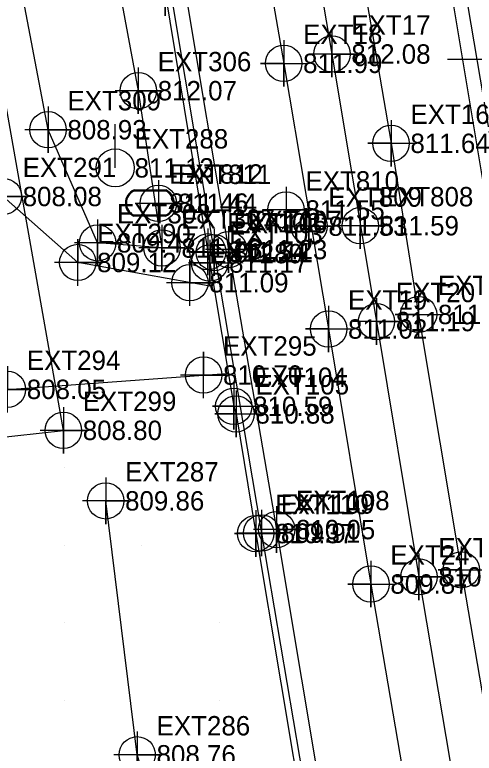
# Model space of a CAD drawing. Extents: x 1762120 to 1766775, y 709485 to 712965.
# Drawn here: x 1763773.6 to 1763832.9, y 712653.2 to 712748.4 of the extents above; entities that cross this region are included whole.
import ezdxf

# ---------------------------------------------------------------- set-up
doc = ezdxf.new("R2010")
doc.units = 0
for name, color, linetype in [('Exist DTM Breakline', 7, 'Continuous'), ('Exist DTM Breakline Cogo Elevation', 7, 'Continuous'), ('Exist DTM Breakline Cogo Number', 7, 'Continuous'), ('Exist DTM Breakline Cogo Point CELL', 7, 'Continuous'), ('Exist DTM Crownline', 7, 'Continuous'), ('Exist DTM Crownline Cogo Elevation', 7, 'Continuous'), ('Exist DTM Crownline Cogo Number', 7, 'Continuous'), ('Exist DTM Crownline Cogo Point CELL', 7, 'Continuous'), ('Exist DTM Drainline', 7, 'Continuous'), ('Exist DTM Drainline Cogo Elevation', 7, 'Continuous'), ('Exist DTM Drainline Cogo Number', 7, 'Continuous'), ('Exist DTM Drainline Cogo Point CELL', 7, 'Continuous'), ('Exist DTM QL2 LIDAR Elevation Point', 7, 'Continuous'), ('Exist Other Culture Fence Line', 7, 'Continuous'), ('Exist Other Culture Fence Line Cogo Elevation', 7, 'Continuous'), ('Exist Other Culture Fence Line Cogo Number', 7, 'Continuous'), ('Exist Other Culture Fence Line Cogo Point CELL', 7, 'Continuous'), ('Exist Roads Curbs', 7, 'Continuous'), ('Exist Roads Curbs Cogo Elevation', 7, 'Continuous'), ('Exist Roads Curbs Cogo Number', 7, 'Continuous'), ('Exist Roads Curbs Cogo Point CELL', 7, 'Continuous'), ('Exist Roads EOP', 7, 'Continuous'), ('Exist Roads EOP Cogo Elevation', 7, 'Continuous'), ('Exist Roads EOP Cogo Number', 7, 'Continuous'), ('Exist Roads EOP Cogo Point CELL', 7, 'Continuous'), ('Exist Roads EOT', 7, 'Continuous'), ('Exist Roads EOT Cogo Elevation', 7, 'Continuous'), ('Exist Roads EOT Cogo Number', 7, 'Continuous'), ('Exist Roads EOT Cogo Point CELL', 7, 'Continuous'), ('Exist Roads Soil', 7, 'Continuous'), ('Exist Roads Soil Cogo Elevation', 7, 'Continuous'), ('Exist Roads Soil Cogo Number', 7, 'Continuous'), ('Exist Roads Soil Cogo Point CELL', 7, 'Continuous'), ('Exist Utilities Power Joint Use Telephone CELL', 7, 'Continuous'), ('Exist Utilities Power Pole CELL', 7, 'Continuous'), ('Exist Utilities Power Pole Cogo Elevation', 7, 'Continuous'), ('Exist Utilities Power Pole Cogo Number', 7, 'Continuous'), ('Exist Utilities Water Meter CELL', 7, 'Continuous'), ('Exist Utilities Water Meter Cogo Elevation', 7, 'Continuous'), ('Exist Utilities Water Meter Cogo Number', 7, 'Continuous'), ('Exist Utilities Water UG Line SUE LOS C Cogo Elevation', 7, 'Continuous'), ('Exist Utilities Water UG Line SUE LOS C Cogo Number', 7, 'Continuous'), ('Exist Utilities Water UG Line SUE LOS C Cogo Point CELL', 7, 'Continuous')]:
    doc.layers.add(name, color=color, linetype=linetype)

msp = doc.modelspace()

# ---------------------------------------------------------------- linework, layer by layer
at = {"layer": 'Exist DTM Breakline'}
for points in [[(1763768.874, 712844.443), (1763776.006, 712808.452), (1763782.443, 712776.817), (1763789.545, 712738.641), (1763792.599, 712718.345), (1763784.294, 712719.006), (1763777.898, 712733.601), (1763771.211, 712768.686), (1763764.647, 712800.553), (1763763.195, 712827.976)], [(1763816.336, 712568.975), (1763813.77, 712594.344), (1763809.401, 712612.263), (1763805.117, 712594.603), (1763799.817, 712620.266), (1763789.401, 712652.954), (1763785.334, 712685.719)]]:
    msp.add_lwpolyline(points, dxfattribs=at)
at = {"layer": 'Exist DTM Breakline Cogo Point CELL'}
for points in [[(1763789.545, 712741.641), (1763789.545, 712735.641), (1763789.545, 712738.641), (1763792.545, 712738.641), (1763786.545, 712738.641)], [(1763777.898, 712736.601), (1763777.898, 712730.601), (1763777.898, 712733.601), (1763780.898, 712733.601), (1763774.898, 712733.601)], [(1763784.294, 712722.006), (1763784.294, 712716.006), (1763784.294, 712719.006), (1763787.294, 712719.006), (1763781.294, 712719.006)], [(1763792.599, 712721.345), (1763792.599, 712715.345), (1763792.599, 712718.345), (1763795.599, 712718.345), (1763789.599, 712718.345)], [(1763785.334, 712688.719), (1763785.334, 712682.719), (1763785.334, 712685.719), (1763788.334, 712685.719), (1763782.334, 712685.719)], [(1763789.401, 712655.954), (1763789.401, 712649.954), (1763789.401, 712652.954), (1763792.401, 712652.954), (1763786.401, 712652.954)]]:
    msp.add_lwpolyline(points, dxfattribs=at)
for centre in [(1763789.545, 712738.641), (1763777.898, 712733.601), (1763784.294, 712719.006), (1763792.599, 712718.345), (1763785.334, 712685.719), (1763789.401, 712652.954)]:
    msp.add_circle(centre, 2.344, dxfattribs=at)
at = {"layer": 'Exist DTM Crownline'}
msp.add_lwpolyline([(1763783.92, 712926.058), (1763790.262, 712887.319), (1763795.183, 712859.532), (1763803.032, 712808.629), (1763808.926, 712776.275), (1763814.523, 712743.371), (1763820.27, 712708.85), (1763825.749, 712675.916), (1763832.222, 712637.522), (1763836.733, 712610.54), (1763843.626, 712568.925)], dxfattribs=at)
at = {"layer": 'Exist DTM Crownline Cogo Point CELL'}
for points in [[(1763814.523, 712746.371), (1763814.523, 712740.371), (1763814.523, 712743.371), (1763817.523, 712743.371), (1763811.523, 712743.371)], [(1763820.27, 712711.85), (1763820.27, 712705.85), (1763820.27, 712708.85), (1763823.27, 712708.85), (1763817.27, 712708.85)], [(1763825.749, 712678.916), (1763825.749, 712672.916), (1763825.749, 712675.916), (1763828.749, 712675.916), (1763822.749, 712675.916)]]:
    msp.add_lwpolyline(points, dxfattribs=at)
for centre in [(1763814.523, 712743.371), (1763820.27, 712708.85), (1763825.749, 712675.916)]:
    msp.add_circle(centre, 2.344, dxfattribs=at)
at = {"layer": 'Exist DTM Drainline'}
for points in [[(1763888.176, 712675.965), (1763883.465, 712673.426), (1763879.421, 712672.239), (1763861.295, 712669.219), (1763855.834, 712669.139), (1763849.992, 712671.404), (1763845.815, 712675.27), (1763843.641, 712680.197), (1763837.254, 712719.085), (1763830.877, 712756.626), (1763824.422, 712795.511), (1763818.53, 712833.611)], [(1763781.288, 712825.282), (1763786.304, 712795.661), (1763793.687, 712751.498), (1763799.331, 712717.754), (1763805.438, 712681.563), (1763811.952, 712643.035), (1763816.532, 712615.56)]]:
    msp.add_lwpolyline(points, dxfattribs=at)
at = {"layer": 'Exist DTM Drainline Cogo Point CELL'}
for points in [[(1763799.331, 712720.754), (1763799.331, 712714.754), (1763799.331, 712717.754), (1763802.331, 712717.754), (1763796.331, 712717.754)], [(1763805.438, 712684.563), (1763805.438, 712678.563), (1763805.438, 712681.563), (1763808.438, 712681.563), (1763802.438, 712681.563)]]:
    msp.add_lwpolyline(points, dxfattribs=at)
for centre in [(1763799.331, 712717.754), (1763805.438, 712681.563)]:
    msp.add_circle(centre, 2.344, dxfattribs=at)
at = {"layer": 'Exist DTM QL2 LIDAR Elevation Point'}
for p, q in [((1763780, 712690), (1763780, 712690)), ((1763790, 712690), (1763790, 712690)), ((1763780, 712680), (1763780, 712680)), ((1763790, 712680), (1763790, 712680)), ((1763780, 712670), (1763780, 712670)), ((1763800, 712670), (1763800, 712670)), ((1763780, 712660), (1763780, 712660)), ((1763800, 712660), (1763800, 712660))]:
    msp.add_line(p, q, dxfattribs=at)
at = {"layer": 'Exist Other Culture Fence Line'}
msp.add_lwpolyline([(1763735.91, 712689.964), (1763779.878, 712694.817), (1763760.773, 712802.969), (1763712.076, 712799.335)], dxfattribs=at)
at = {"layer": 'Exist Other Culture Fence Line Cogo Point CELL'}
msp.add_lwpolyline([(1763779.878, 712697.817), (1763779.878, 712691.817), (1763779.878, 712694.817), (1763782.878, 712694.817), (1763776.878, 712694.817)], dxfattribs=at)
msp.add_circle((1763779.878, 712694.817), 2.344, dxfattribs=at)
at = {"layer": 'Exist Roads Curbs'}
msp.add_lwpolyline([(1763764.468, 712921.993), (1763771.224, 712881.371), (1763777.799, 712842.52), (1763785.017, 712799.156), (1763793.002, 712751.297), (1763798.517, 712717.85), (1763798.751, 712716.41), (1763801.856, 712697.916), (1763802.154, 712696.936), (1763804.688, 712681.498), (1763811.149, 712642.967), (1763816.501, 712611.824), (1763823.372, 712570.121)], dxfattribs=at)
at = {"layer": 'Exist Roads Curbs Cogo Point CELL'}
for points in [[(1763793.002, 712754.297), (1763793.002, 712748.297), (1763793.002, 712751.297), (1763790.272, 712751.297), (1763796.002, 712751.297)], [(1763798.517, 712720.85), (1763798.517, 712714.85), (1763798.517, 712717.85), (1763795.787, 712717.85), (1763801.517, 712717.85)], [(1763798.751, 712719.41), (1763798.751, 712713.41), (1763798.751, 712716.41), (1763796.021, 712716.41), (1763801.751, 712716.41)], [(1763801.856, 712700.916), (1763801.856, 712694.916), (1763801.856, 712697.916), (1763799.126, 712697.916), (1763804.856, 712697.916)], [(1763802.154, 712699.936), (1763802.154, 712693.936), (1763802.154, 712696.936), (1763799.424, 712696.936), (1763805.154, 712696.936)], [(1763804.688, 712684.498), (1763804.688, 712678.498), (1763804.688, 712681.498), (1763801.958, 712681.498), (1763807.688, 712681.498)]]:
    msp.add_lwpolyline(points, dxfattribs=at)
for centre in [(1763798.517, 712717.85), (1763798.751, 712716.41), (1763801.856, 712697.916), (1763802.154, 712696.936), (1763804.688, 712681.498)]:
    msp.add_circle(centre, 2.344, dxfattribs=at)
at = {"layer": 'Exist Roads EOP'}
for points in [[(1763767.083, 712922.223), (1763773.823, 712881.974), (1763780.335, 712842.895), (1763788.848, 712791.154), (1763795.539, 712751.806), (1763801.2, 712718.139), (1763807.385, 712682.013), (1763813.812, 712643.387), (1763818.936, 712612.35), (1763825.965, 712570.729)], [(1763872.939, 712669.264), (1763861.771, 712667.397), (1763856.129, 712667.205), (1763850.394, 712669.068), (1763848.283, 712670.385), (1763843.436, 712675.406), (1763841.767, 712679.86), (1763835.931, 712715.544), (1763829.184, 712756.072), (1763822.427, 712796.443), (1763817.324, 712826.974), (1763816.07, 712838.811), (1763818.954, 712848.93), (1763823.982, 712854.424), (1763830.822, 712857.794), (1763839.256, 712859.239)]]:
    msp.add_lwpolyline(points, dxfattribs=at)
at = {"layer": 'Exist Roads EOP Cogo Point CELL'}
for points in [[(1763801.2, 712721.139), (1763801.2, 712715.139), (1763801.2, 712718.139), (1763804.2, 712718.139), (1763798.2, 712718.139)], [(1763807.385, 712685.013), (1763807.385, 712679.013), (1763807.385, 712682.013), (1763810.385, 712682.013), (1763804.385, 712682.013)]]:
    msp.add_lwpolyline(points, dxfattribs=at)
for centre in [(1763801.2, 712718.139), (1763807.385, 712682.013)]:
    msp.add_circle(centre, 2.344, dxfattribs=at)
at = {"layer": 'Exist Roads EOT'}
for points in [[(1763789.832, 712926.884), (1763795.992, 712888.052), (1763800.75, 712859.942), (1763807.254, 712820.955), (1763816.86, 712762.721), (1763822.148, 712731.849), (1763825.695, 712709.767), (1763831.213, 712676.817), (1763837.744, 712638.56), (1763842.2, 712611.183), (1763849.139, 712569.759)], [(1763777.488, 712924.55), (1763781.487, 712903.204), (1763789.164, 712854.697), (1763797.205, 712808.308), (1763802.541, 712775.258), (1763808.303, 712742.168), (1763814.095, 712707.894), (1763819.559, 712674.99), (1763826.1, 712636.377), (1763830.485, 712609.669), (1763837.441, 712567.81)]]:
    msp.add_lwpolyline(points, dxfattribs=at)
at = {"layer": 'Exist Roads EOT Cogo Point CELL'}
for points in [[(1763808.303, 712745.168), (1763808.303, 712739.168), (1763808.303, 712742.168), (1763805.303, 712742.168), (1763811.303, 712742.168)], [(1763822.148, 712734.849), (1763822.148, 712728.849), (1763822.148, 712731.849), (1763819.148, 712731.849), (1763825.148, 712731.849)], [(1763825.695, 712712.767), (1763825.695, 712706.767), (1763825.695, 712709.767), (1763822.695, 712709.767), (1763828.695, 712709.767)], [(1763814.095, 712710.894), (1763814.095, 712704.894), (1763814.095, 712707.894), (1763811.095, 712707.894), (1763817.095, 712707.894)], [(1763831.213, 712679.817), (1763831.213, 712673.817), (1763831.213, 712676.817), (1763828.213, 712676.817), (1763834.213, 712676.817)], [(1763819.559, 712677.99), (1763819.559, 712671.99), (1763819.559, 712674.99), (1763816.559, 712674.99), (1763822.559, 712674.99)]]:
    msp.add_lwpolyline(points, dxfattribs=at)
for centre in [(1763808.303, 712742.168), (1763822.148, 712731.849), (1763825.695, 712709.767), (1763814.095, 712707.894), (1763831.213, 712676.817), (1763819.559, 712674.99)]:
    msp.add_circle(centre, 2.344, dxfattribs=at)
at = {"layer": 'Exist Roads Soil'}
msp.add_lwpolyline([(1763799.032, 712713.358), (1763781.732, 712716.474), (1763772.126, 712724.99), (1763746.815, 712707.424), (1763748.657, 712698.365), (1763772.656, 712700.105), (1763800.874, 712702.164)], dxfattribs=at)
at = {"layer": 'Exist Roads Soil Cogo Point CELL'}
for points in [[(1763772.126, 712721.99), (1763772.126, 712727.99), (1763772.126, 712724.99), (1763775.126, 712724.99), (1763769.126, 712724.99)], [(1763781.732, 712713.474), (1763781.732, 712719.474), (1763781.732, 712716.474), (1763784.732, 712716.474), (1763778.732, 712716.474)], [(1763796.202, 712710.868), (1763796.202, 712716.868), (1763796.202, 712713.868), (1763799.202, 712713.868), (1763793.202, 712713.868)], [(1763797.973, 712698.952), (1763797.973, 712704.952), (1763797.973, 712701.952), (1763800.973, 712701.952), (1763794.973, 712701.952)], [(1763772.656, 712697.105), (1763772.656, 712703.105), (1763772.656, 712700.105), (1763775.656, 712700.105), (1763769.656, 712700.105)]]:
    msp.add_lwpolyline(points, dxfattribs=at)
for centre in [(1763772.126, 712724.99), (1763781.732, 712716.474), (1763796.202, 712713.868), (1763797.973, 712701.952), (1763772.656, 712700.105)]:
    msp.add_circle(centre, 2.344, dxfattribs=at)
at = {"layer": 'Exist Utilities Power Joint Use Telephone CELL'}
msp.add_lwpolyline([(1763829.409, 712742.723), (1763840.746, 712742.685), (1763835.346, 712742.703), (1763835.346, 712748.348)], dxfattribs=at)
at = {"layer": 'Exist Utilities Power Pole CELL'}
for q in [(1763786.564, 712734.304), (1763786.564, 712728.679)]:
    msp.add_line((1763786.564, 712728.679), q, dxfattribs=at)
msp.add_circle((1763786.564, 712728.679), 2.45, dxfattribs=at)
at = {"layer": 'Exist Utilities Water Meter CELL'}
msp.add_line((1763791.036, 712724.139), (1763791.036, 712724.139), dxfattribs=at)
for points in [[(1763788.998, 712725.839), (1763793.073, 712725.839)], [(1763788.998, 712725.701), (1763793.073, 712725.701)], [(1763793.073, 712722.576), (1763788.974, 712722.576)], [(1763793.073, 712722.439), (1763788.974, 712722.439)]]:
    msp.add_lwpolyline(points, dxfattribs=at)
for centre, radius, start, end in [((1763789.729, 712724.134), 1.855, 113.17804, 245.97939), ((1763792.329, 712724.14), 1.856, 293.64832, 66.30838), ((1763789.74, 712724.133), 1.735, 115.30093, 243.78236), ((1763792.341, 712724.139), 1.726, 295.12717, 64.87283)]:
    msp.add_arc(centre, radius, start, end, dxfattribs=at)
at = {"layer": 'Exist Utilities Water UG Line SUE LOS C Cogo Point CELL'}
for points in [[(1763792.137, 712727.1), (1763792.137, 712721.1), (1763792.137, 712724.1), (1763795.137, 712724.1), (1763789.137, 712724.1)], [(1763808.602, 712726.249), (1763808.602, 712720.249), (1763808.602, 712723.249), (1763811.602, 712723.249), (1763805.602, 712723.249)], [(1763811.561, 712724.164), (1763811.561, 712718.164), (1763811.561, 712721.164), (1763814.561, 712721.164), (1763808.561, 712721.164)], [(1763818.184, 712724.215), (1763818.184, 712718.215), (1763818.184, 712721.215), (1763821.184, 712721.215), (1763815.184, 712721.215)]]:
    msp.add_lwpolyline(points, dxfattribs=at)
for centre in [(1763792.137, 712724.1), (1763808.602, 712723.249), (1763811.561, 712721.164), (1763818.184, 712721.215)]:
    msp.add_circle(centre, 2.344, dxfattribs=at)

# ---------------------------------------------------------------- texts
at = {"layer": 'Exist DTM Breakline Cogo Elevation'}
for s, p in [('812.07', (1763792.045, 712737.391)), ('808.93', (1763780.398, 712732.351)), ('809.47', (1763786.794, 712717.756)), ('811.16', (1763795.099, 712717.095)), ('809.86', (1763787.834, 712684.469)), ('808.76', (1763791.901, 712651.704))]:
    msp.add_text(s, height=2.5, dxfattribs=at).set_placement(p)
at = {"layer": 'Exist DTM Breakline Cogo Number'}
for s, p in [('EXT306', (1763792.045, 712741.141)), ('EXT309', (1763780.398, 712736.101)), ('EXT308', (1763786.794, 712721.506)), ('EXT307', (1763795.099, 712720.845)), ('EXT287', (1763787.834, 712688.219)), ('EXT286', (1763791.901, 712655.454))]:
    msp.add_text(s, height=2.5, dxfattribs=at).set_placement(p)
at = {"layer": 'Exist DTM Crownline Cogo Elevation'}
for s, p in [('812.08', (1763817.023, 712742.121)), ('811.19', (1763822.77, 712707.6)), ('810.05', (1763828.249, 712674.666))]:
    msp.add_text(s, height=2.5, dxfattribs=at).set_placement(p)
at = {"layer": 'Exist DTM Crownline Cogo Number'}
for s, p in [('EXT17', (1763817.023, 712745.871)), ('EXT20', (1763822.77, 712711.35)), ('EXT23', (1763828.249, 712678.416))]:
    msp.add_text(s, height=2.5, dxfattribs=at).set_placement(p)
at = {"layer": 'Exist DTM Drainline Cogo Elevation'}
for s, p in [('811.11', (1763801.831, 712716.504)), ('809.91', (1763807.938, 712680.313))]:
    msp.add_text(s, height=2.5, dxfattribs=at).set_placement(p)
at = {"layer": 'Exist DTM Drainline Cogo Number'}
for s, p in [('EXT106', (1763801.831, 712720.254)), ('EXT109', (1763807.938, 712684.063))]:
    msp.add_text(s, height=2.5, dxfattribs=at).set_placement(p)
at = {"layer": 'Exist Other Culture Fence Line Cogo Elevation'}
msp.add_text('808.80', height=2.5, dxfattribs=at).set_placement((1763782.378, 712693.567))
at = {"layer": 'Exist Other Culture Fence Line Cogo Number'}
msp.add_text('EXT299', height=2.5, dxfattribs=at).set_placement((1763782.378, 712697.317))
at = {"layer": 'Exist Roads Curbs Cogo Elevation'}
for s, p in [('811.54', (1763801.017, 712716.6)), ('811.17', (1763801.251, 712715.16)), ('810.59', (1763804.356, 712696.666)), ('810.88', (1763804.654, 712695.686)), ('810.37', (1763807.188, 712680.248))]:
    msp.add_text(s, height=2.5, dxfattribs=at).set_placement(p)
at = {"layer": 'Exist Roads Curbs Cogo Number'}
for s, p in [('EXT102', (1763801.017, 712720.35)), ('EXT103', (1763801.251, 712718.91)), ('EXT104', (1763804.356, 712700.416)), ('EXT105', (1763804.654, 712699.436)), ('EXT110', (1763807.188, 712683.998))]:
    msp.add_text(s, height=2.5, dxfattribs=at).set_placement(p)
at = {"layer": 'Exist Roads EOP Cogo Elevation'}
for s, p in [('811.23', (1763803.7, 712716.889)), ('810.05', (1763809.885, 712680.763))]:
    msp.add_text(s, height=2.5, dxfattribs=at).set_placement(p)
at = {"layer": 'Exist Roads EOP Cogo Number'}
for s, p in [('EXT107', (1763803.7, 712720.639)), ('EXT108', (1763809.885, 712684.513))]:
    msp.add_text(s, height=2.5, dxfattribs=at).set_placement(p)
at = {"layer": 'Exist Roads EOT Cogo Elevation'}
for s, p in [('811.99', (1763810.803, 712740.918)), ('811.64', (1763824.648, 712730.599)), ('811.11', (1763828.195, 712708.517)), ('811.02', (1763816.595, 712706.644)), ('809.87', (1763822.059, 712673.74))]:
    msp.add_text(s, height=2.5, dxfattribs=at).set_placement(p)
at = {"layer": 'Exist Roads EOT Cogo Number'}
for s, p in [('EXT18', (1763810.803, 712744.668)), ('EXT16', (1763824.648, 712734.349)), ('EXT21', (1763828.195, 712712.267)), ('EXT19', (1763816.595, 712710.394)), ('EXT24', (1763822.059, 712677.49))]:
    msp.add_text(s, height=2.5, dxfattribs=at).set_placement(p)
at = {"layer": 'Exist Roads Soil Cogo Elevation'}
for s, p in [('808.08', (1763774.626, 712723.74)), ('809.12', (1763784.232, 712715.224)), ('811.09', (1763798.702, 712712.618)), ('810.70', (1763800.473, 712700.702)), ('808.05', (1763775.156, 712698.855))]:
    msp.add_text(s, height=2.5, dxfattribs=at).set_placement(p)
at = {"layer": 'Exist Roads Soil Cogo Number'}
for s, p in [('EXT291', (1763774.626, 712727.49)), ('EXT290', (1763784.232, 712718.974)), ('EXT289', (1763798.702, 712716.368)), ('EXT295', (1763800.473, 712704.452)), ('EXT294', (1763775.156, 712702.605))]:
    msp.add_text(s, height=2.5, dxfattribs=at).set_placement(p)
at = {"layer": 'Exist Utilities Power Pole Cogo Elevation'}
msp.add_text('811.13', height=2.5, dxfattribs=at).set_placement((1763789.064, 712727.429))
at = {"layer": 'Exist Utilities Power Pole Cogo Number'}
msp.add_text('EXT288', height=2.5, dxfattribs=at).set_placement((1763789.064, 712731.179))
at = {"layer": 'Exist Utilities Water Meter Cogo Elevation'}
msp.add_text('811.46', height=2.5, dxfattribs=at).set_placement((1763793.536, 712722.889))
at = {"layer": 'Exist Utilities Water Meter Cogo Number'}
msp.add_text('EXT812', height=2.5, dxfattribs=at).set_placement((1763793.536, 712726.639))
at = {"layer": 'Exist Utilities Water UG Line SUE LOS C Cogo Elevation'}
for s, p in [('811.44', (1763794.637, 712722.85)), ('811.55', (1763811.102, 712721.999)), ('811.53', (1763814.061, 712719.914)), ('811.59', (1763820.684, 712719.965))]:
    msp.add_text(s, height=2.5, dxfattribs=at).set_placement(p)
at = {"layer": 'Exist Utilities Water UG Line SUE LOS C Cogo Number'}
for s, p in [('EXT811', (1763794.637, 712726.6)), ('EXT810', (1763811.102, 712725.749)), ('EXT809', (1763814.061, 712723.664)), ('EXT808', (1763820.684, 712723.715))]:
    msp.add_text(s, height=2.5, dxfattribs=at).set_placement(p)

doc.saveas('drawing.dxf')
